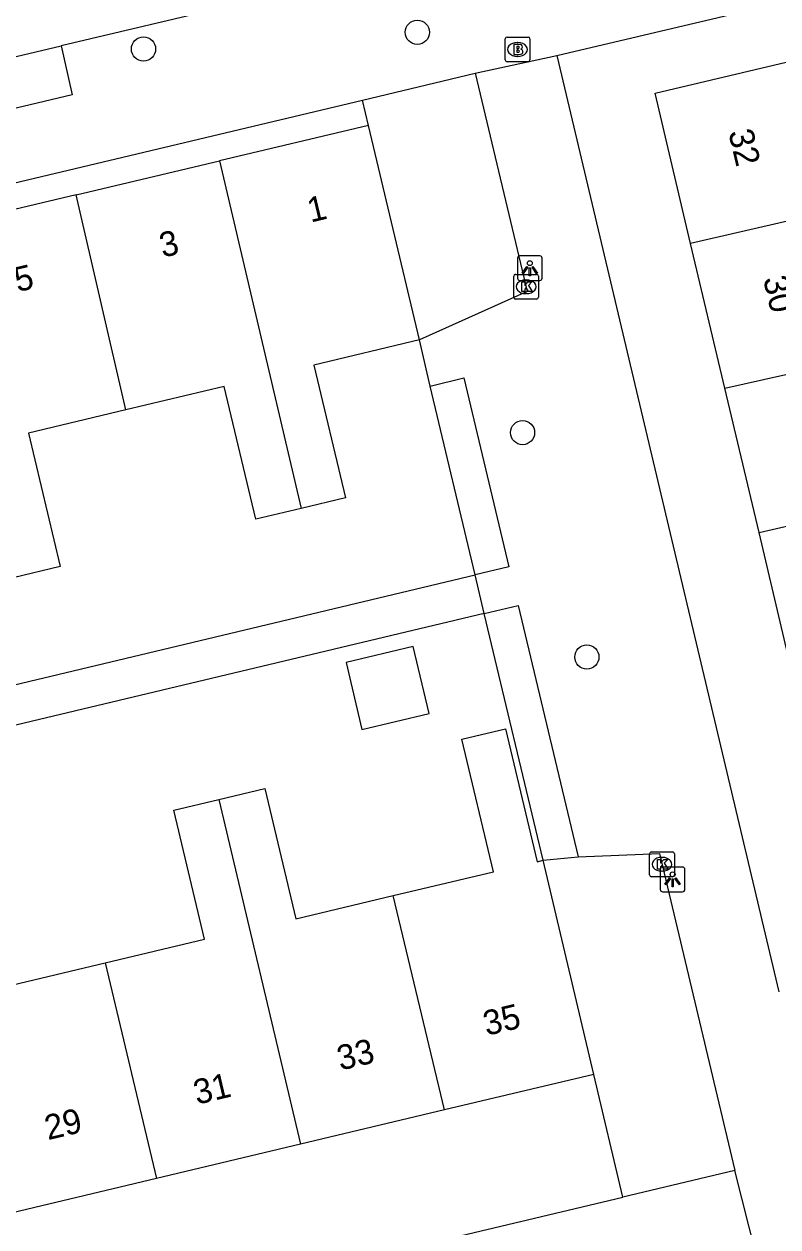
# Model space of a CAD drawing. Extents: x 158038 to 159242, y 380133 to 381214.
# Drawn here: x 158513.7 to 158544.2, y 380808.39 to 380857.02 of the extents above; entities that cross this region are included whole.
import ezdxf

# ---------------------------------------------------------------- set-up
doc = ezdxf.new("R2010")
doc.units = 0
for name, color, linetype in [('IMGEO_Boom', 7, 'Continuous'), ('IMGEO_Brandkraan', 7, 'Continuous'), ('IMGEO_Groenvoorziening', 7, 'Continuous'), ('IMGEO_Kolk', 7, 'Continuous'), ('IMGEO_Lichtpunt', 7, 'Continuous'), ('IMGEO_Pand', 7, 'Continuous'), ('IMGEO_Pand_nummerreeks', 7, 'Continuous'), ('IMGEO_Rijbaan_lokaal_open', 7, 'Continuous'), ('IMGEO_Voetpad_open', 7, 'Continuous')]:
    doc.layers.add(name, color=color, linetype=linetype)

msp = doc.modelspace()

# ---------------------------------------------------------------- linework, layer by layer
at = {"layer": 'IMGEO_Boom'}
for centre in [(158529.61, 380856.689), (158518.534, 380856.012), (158533.867, 380840.506), (158536.467, 380831.434)]:
    msp.add_circle(centre, 0.489, dxfattribs=at)
at = {"layer": 'IMGEO_Brandkraan'}
for p, q in [((158533.164, 380855.569), (158533.164, 380856.421)), ((158533.239, 380856.495), (158534.091, 380856.495)), ((158534.165, 380856.421), (158534.165, 380855.569)), ((158533.652, 380856.275), (158533.677, 380856.275)), ((158534.091, 380855.495), (158533.239, 380855.495)), ((158533.675, 380855.715), (158533.65, 380855.715))]:
    msp.add_line(p, q, dxfattribs=at)
for points in [[(158533.164, 380855.569), (158533.164, 380856.421)], [(158533.239, 380856.495), (158534.091, 380856.495)], [(158534.165, 380856.421), (158534.165, 380855.569)], [(158533.512, 380856.195), (158533.512, 380855.795), (158533.725, 380855.795)], [(158533.743, 380856.195), (158533.512, 380856.195)], [(158533.691, 380856.114), (158533.637, 380856.114), (158533.637, 380856.038)], [(158533.637, 380856.038), (158533.69, 380856.038)], [(158533.699, 380855.962), (158533.637, 380855.962), (158533.637, 380855.881)], [(158533.637, 380855.881), (158533.699, 380855.881)], [(158534.091, 380855.495), (158533.239, 380855.495)]]:
    msp.add_lwpolyline(points, dxfattribs=at)
for centre, radius, start, end in [((158533.241, 380856.419), 0.0765, 91.552, 178.448), ((158533.241, 380856.419), 0.0765, 91.552, 178.448), ((158534.089, 380856.419), 0.0765, 1.552, 88.448), ((158534.089, 380856.419), 0.0765, 1.552, 88.448), ((158533.692, 380856.076), 0.0379, 267.8285, 90.9355), ((158533.7, 380855.921), 0.0404, 269.8759, 90.5077), ((158533.747, 380856.05), 0.145, 59.4692, 91.5367), ((158533.772, 380856.097), 0.0922, 285.5137, 58.1501), ((158533.777, 380855.905), 0.105, 301.3115, 78.989), ((158533.241, 380855.571), 0.0765, 181.552, 268.448), ((158533.241, 380855.571), 0.0765, 181.552, 268.448), ((158533.731, 380856.046), 0.251, 268.6676, 293.5347), ((158534.089, 380855.571), 0.0765, 271.552, 358.448), ((158534.089, 380855.571), 0.0765, 271.552, 358.448)]:
    msp.add_arc(centre, radius, start, end, dxfattribs=at)
for centre, major_axis, ratio, start_param, end_param in [((158533.651, 380855.995), (-0.387, 0.002), 0.722429, 4.712389, 7.853982), ((158533.676, 380855.995), (-0.39, 0.002), 0.717154, 1.570796, 4.712389)]:
    msp.add_ellipse(centre, major_axis=major_axis, ratio=ratio, start_param=start_param, end_param=end_param, dxfattribs=at)
at = {"layer": 'IMGEO_Groenvoorziening'}
for points in [[(158527.629, 380852.918), (158527.386, 380853.947)], [(158531.947, 380834.753), (158530.127, 380842.389)], [(158534.696, 380823.215), (158532.318, 380833.196)], [(158534.696, 380823.215), (158536.114, 380823.358)], [(158537.922, 380809.603), (158536.754, 380814.56)]]:
    msp.add_lwpolyline(points, dxfattribs=at)
at = {"layer": 'IMGEO_Kolk'}
for p, q in [((158533.51, 380845.977), (158533.51, 380846.829)), ((158533.585, 380846.903), (158534.437, 380846.903)), ((158533.998, 380846.683), (158534.023, 380846.683)), ((158534.511, 380846.829), (158534.511, 380845.977)), ((158534.021, 380846.123), (158533.996, 380846.123)), ((158534.437, 380845.903), (158533.585, 380845.903)), ((158539.006, 380822.628), (158539.006, 380823.48)), ((158539.081, 380823.554), (158539.933, 380823.554)), ((158539.494, 380823.334), (158539.519, 380823.334)), ((158540.007, 380823.48), (158540.007, 380822.628)), ((158539.933, 380822.554), (158539.081, 380822.554)), ((158539.517, 380822.774), (158539.492, 380822.774))]:
    msp.add_line(p, q, dxfattribs=at)
for points in [[(158533.51, 380845.977), (158533.51, 380846.829)], [(158533.585, 380846.903), (158534.437, 380846.903)], [(158534.511, 380846.829), (158534.511, 380845.977)], [(158533.831, 380846.603), (158533.954, 380846.603), (158533.954, 380846.452), (158534.084, 380846.603), (158534.248, 380846.603), (158534.102, 380846.452), (158534.255, 380846.203), (158534.103, 380846.203), (158534.018, 380846.367), (158533.954, 380846.3), (158533.954, 380846.203), (158533.831, 380846.203), (158533.831, 380846.603)], [(158534.437, 380845.903), (158533.585, 380845.903)], [(158539.006, 380822.628), (158539.006, 380823.48)], [(158539.081, 380823.554), (158539.933, 380823.554)], [(158540.007, 380823.48), (158540.007, 380822.628)], [(158539.327, 380823.254), (158539.45, 380823.254), (158539.45, 380823.103), (158539.58, 380823.254), (158539.744, 380823.254), (158539.598, 380823.103), (158539.751, 380822.854), (158539.599, 380822.854), (158539.514, 380823.018), (158539.45, 380822.951), (158539.45, 380822.854), (158539.327, 380822.854), (158539.327, 380823.254)], [(158539.933, 380822.554), (158539.081, 380822.554)]]:
    msp.add_lwpolyline(points, dxfattribs=at)
for centre, start, end in [((158533.587, 380846.827), 91.552, 178.448), ((158533.587, 380846.827), 91.552, 178.448), ((158534.435, 380846.827), 1.552, 88.448), ((158534.435, 380846.827), 1.552, 88.448), ((158533.587, 380845.979), 181.552, 268.448), ((158533.587, 380845.979), 181.552, 268.448), ((158534.435, 380845.979), 271.552, 358.448), ((158534.435, 380845.979), 271.552, 358.448), ((158539.083, 380823.478), 91.552, 178.448), ((158539.083, 380823.478), 91.552, 178.448), ((158539.931, 380823.478), 1.552, 88.448), ((158539.931, 380823.478), 1.552, 88.448), ((158539.083, 380822.63), 181.552, 268.448), ((158539.083, 380822.63), 181.552, 268.448), ((158539.931, 380822.63), 271.552, 358.448), ((158539.931, 380822.63), 271.552, 358.448)]:
    msp.add_arc(centre, 0.0765, start, end, dxfattribs=at)
for centre, major_axis, ratio, start_param, end_param in [((158533.997, 380846.403), (-0.387, 0.002), 0.722429, 4.712389, 7.853982), ((158534.022, 380846.403), (-0.39, 0.002), 0.717154, 1.570796, 4.712389), ((158539.493, 380823.054), (-0.387, 0.002), 0.722429, 4.712389, 7.853982), ((158539.518, 380823.054), (-0.39, 0.002), 0.717154, 1.570796, 4.712389)]:
    msp.add_ellipse(centre, major_axis=major_axis, ratio=ratio, start_param=start_param, end_param=end_param, dxfattribs=at)
at = {"layer": 'IMGEO_Lichtpunt'}
for p, q in [((158534.565, 380847.65), (158533.757, 380847.65)), ((158534.565, 380847.65), (158533.757, 380847.65)), ((158533.663, 380847.555), (158533.663, 380846.748)), ((158533.663, 380847.555), (158533.663, 380846.748)), ((158534.659, 380846.748), (158534.659, 380847.555)), ((158534.659, 380846.748), (158534.659, 380847.555)), ((158533.757, 380846.654), (158534.565, 380846.654)), ((158533.757, 380846.654), (158534.565, 380846.654)), ((158539.437, 380822.848), (158539.437, 380822.041)), ((158539.437, 380822.848), (158539.437, 380822.041)), ((158540.339, 380822.943), (158539.531, 380822.943)), ((158540.339, 380822.943), (158539.531, 380822.943)), ((158540.433, 380822.041), (158540.433, 380822.848)), ((158540.433, 380822.041), (158540.433, 380822.848)), ((158539.531, 380821.947), (158540.339, 380821.947)), ((158539.531, 380821.947), (158540.339, 380821.947))]:
    msp.add_line(p, q, dxfattribs=at)
for points in [[(158534.037, 380847.219), (158534.076, 380847.191), (158533.888, 380846.929), (158533.85, 380846.956), (158534.037, 380847.219)], [(158534.139, 380847.171), (158534.186, 380847.171), (158534.186, 380846.849), (158534.139, 380846.849), (158534.139, 380847.171)], [(158534.249, 380847.191), (158534.287, 380847.218), (158534.474, 380846.956), (158534.435, 380846.928), (158534.249, 380847.191)], [(158539.811, 380822.512), (158539.85, 380822.484), (158539.662, 380822.222), (158539.624, 380822.249), (158539.811, 380822.512)], [(158539.913, 380822.464), (158539.96, 380822.464), (158539.96, 380822.142), (158539.913, 380822.142), (158539.913, 380822.464)], [(158540.023, 380822.484), (158540.061, 380822.511), (158540.248, 380822.249), (158540.209, 380822.221), (158540.023, 380822.484)]]:
    msp.add_lwpolyline(points, dxfattribs=at)
for centre in [(158534.162, 380847.353), (158539.936, 380822.646)]:
    msp.add_circle(centre, 0.0994, dxfattribs=at)
for centre, start, end in [((158533.757, 380847.555), 90, 180), ((158533.757, 380847.555), 90, 180), ((158534.565, 380847.555), 0, 90), ((158534.565, 380847.555), 0, 90), ((158533.757, 380846.748), 180, 270), ((158533.757, 380846.748), 180, 270), ((158534.565, 380846.748), 270, 0), ((158534.565, 380846.748), 270, 360), ((158539.531, 380822.848), 90, 180), ((158539.531, 380822.848), 90, 180), ((158540.339, 380822.848), 0, 90), ((158540.339, 380822.848), 0, 90), ((158539.531, 380822.041), 180, 270), ((158539.531, 380822.041), 180, 270), ((158540.339, 380822.041), 270, 0), ((158540.339, 380822.041), 270, 360)]:
    msp.add_arc(centre, 0.0946, start, end, dxfattribs=at)
at = {"layer": 'IMGEO_Pand'}
for points in [[(158540.664, 380848.149), (158539.224, 380854.225), (158548.057, 380856.318), (158549.072, 380852.035), (158550.463, 380852.365)], [(158527.629, 380852.918), (158521.603, 380851.489)], [(158529.701, 380844.249), (158527.629, 380852.918)], [(158550.463, 380852.365), (158550.902, 380850.509), (158540.664, 380848.149)], [(158515.808, 380850.114), (158521.603, 380851.489)], [(158521.603, 380851.489), (158524.908, 380837.439)], [(158515.808, 380850.114), (158510.012, 380848.739)], [(158517.824, 380841.421), (158515.808, 380850.114)], [(158542.048, 380842.307), (158540.664, 380848.149)], [(158529.701, 380844.249), (158525.424, 380843.227), (158526.705, 380837.869), (158524.908, 380837.439)], [(158542.048, 380842.307), (158550.887, 380844.279)], [(158524.908, 380837.439), (158523.075, 380837.001), (158521.792, 380842.37), (158517.824, 380841.421)], [(158543.432, 380836.465), (158542.048, 380842.307)], [(158517.824, 380841.421), (158513.881, 380840.479), (158515.167, 380835.096), (158513.257, 380834.639)], [(158543.432, 380836.465), (158557.666, 380839.75)], [(158544.817, 380830.623), (158543.432, 380836.465)], [(158526.728, 380831.216), (158527.372, 380828.502), (158530.087, 380829.147), (158529.443, 380831.861), (158526.728, 380831.216)], [(158528.63, 380821.788), (158532.689, 380822.753), (158531.417, 380828.107), (158533.175, 380828.525), (158534.452, 380823.156), (158534.696, 380823.215)], [(158521.579, 380825.677), (158523.439, 380826.119), (158524.691, 380820.852), (158528.63, 380821.788)], [(158516.987, 380819.069), (158520.999, 380820.023), (158519.757, 380825.244), (158521.579, 380825.677)], [(158521.579, 380825.677), (158524.882, 380811.738)], [(158509.938, 380822.906), (158511.72, 380823.33), (158512.96, 380818.112), (158516.987, 380819.069)], [(158536.754, 380814.56), (158534.696, 380823.215)], [(158530.707, 380813.123), (158528.63, 380821.788)], [(158516.987, 380819.069), (158519.058, 380810.353)], [(158536.754, 380814.56), (158530.707, 380813.123)], [(158530.707, 380813.123), (158524.882, 380811.738)], [(158524.882, 380811.738), (158519.058, 380810.353)], [(158519.058, 380810.353), (158513.233, 380808.969)]]:
    msp.add_lwpolyline(points, dxfattribs=at)
at = {"layer": 'IMGEO_Rijbaan_lokaal_open'}
for points in [[(158534.08, 380860.599), (158522.175, 380857.778), (158515.207, 380856.135)], [(158472.473, 380846.056), (158500, 380852.548), (158515.207, 380856.135)]]:
    msp.add_lwpolyline(points, dxfattribs=at)
at = {"layer": 'IMGEO_Voetpad_open'}
for points in [[(158535.255, 380855.756), (158554.603, 380860.32)], [(158515.207, 380856.135), (158515.654, 380854.159), (158500, 380850.436), (158472.957, 380844.003)], [(158531.949, 380855.031), (158535.255, 380855.756)], [(158535.255, 380855.756), (158544.228, 380817.894)], [(158527.386, 380853.947), (158531.949, 380855.031)], [(158531.949, 380855.031), (158534.055, 380846.214), (158529.701, 380844.249)], [(158431.67, 380831.273), (158431.507, 380831.934), (158492.147, 380846.362), (158492.306, 380845.603), (158500, 380847.433), (158527.386, 380853.947)], [(158530.127, 380842.389), (158529.701, 380844.249)], [(158530.127, 380842.389), (158531.489, 380842.714), (158533.313, 380835.079), (158531.947, 380834.753)], [(158481.491, 380820.412), (158497.564, 380824.113), (158497.048, 380826.435), (158531.947, 380834.753)], [(158532.318, 380833.196), (158531.947, 380834.753)], [(158532.318, 380833.196), (158533.686, 380833.522), (158536.114, 380823.358)], [(158532.318, 380833.196), (158520.157, 380830.298), (158501.147, 380825.768), (158505.739, 380806.499), (158506.764, 380802.198)], [(158536.114, 380823.358), (158539.402, 380823.491), (158542.451, 380810.679)], [(158542.451, 380810.679), (158537.922, 380809.603)], [(158543.309, 380807.269), (158542.451, 380810.679)], [(158506.764, 380802.198), (158510.799, 380803.157), (158537.922, 380809.603)]]:
    msp.add_lwpolyline(points, dxfattribs=at)

# ---------------------------------------------------------------- texts
at = {"layer": 'IMGEO_Pand_nummerreeks'}
for s, rotation, p in [('32', 283.3305, (158542.186, 380852.652)), ('1', 13.3531, (158525.294, 380848.992)), ('3', 13.3531, (158519.311, 380847.573)), ('5', 13.3531, (158513.439, 380846.179)), ('30', 283.3305, (158543.59, 380846.726)), ('35', 13.3719, (158532.41, 380816.117)), ('33', 13.3719, (158526.497, 380814.712)), ('31', 13.3719, (158520.693, 380813.332)), ('29', 13.3719, (158514.669, 380811.9))]:
    msp.add_text(s, height=1, rotation=rotation, dxfattribs=at).set_placement(p)

doc.saveas('drawing.dxf')
